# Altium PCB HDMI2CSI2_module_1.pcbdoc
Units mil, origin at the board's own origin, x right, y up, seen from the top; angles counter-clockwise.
Board outline 4245 x 2835 mil, 4 copper layers (Top Layer, Inner1, Inner2, Bottom Layer); 51 components, 44 nets, 240 pads, 137 vias.
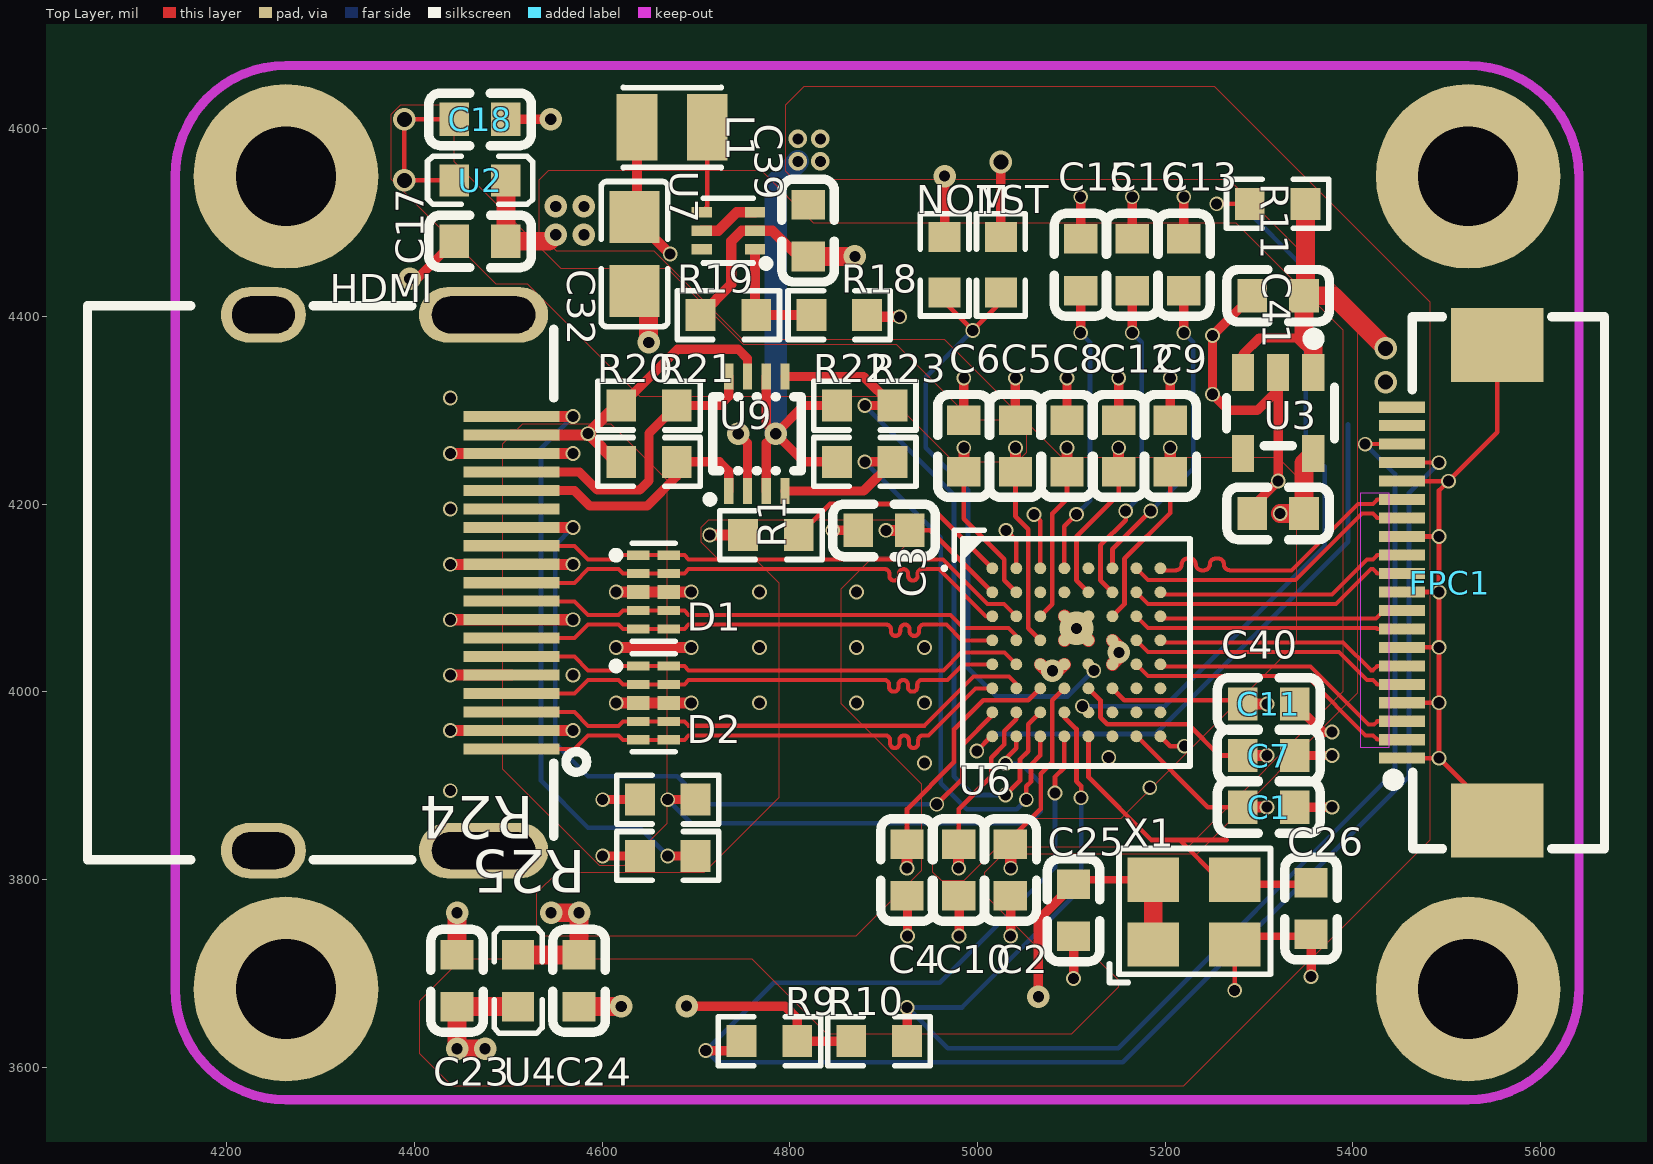
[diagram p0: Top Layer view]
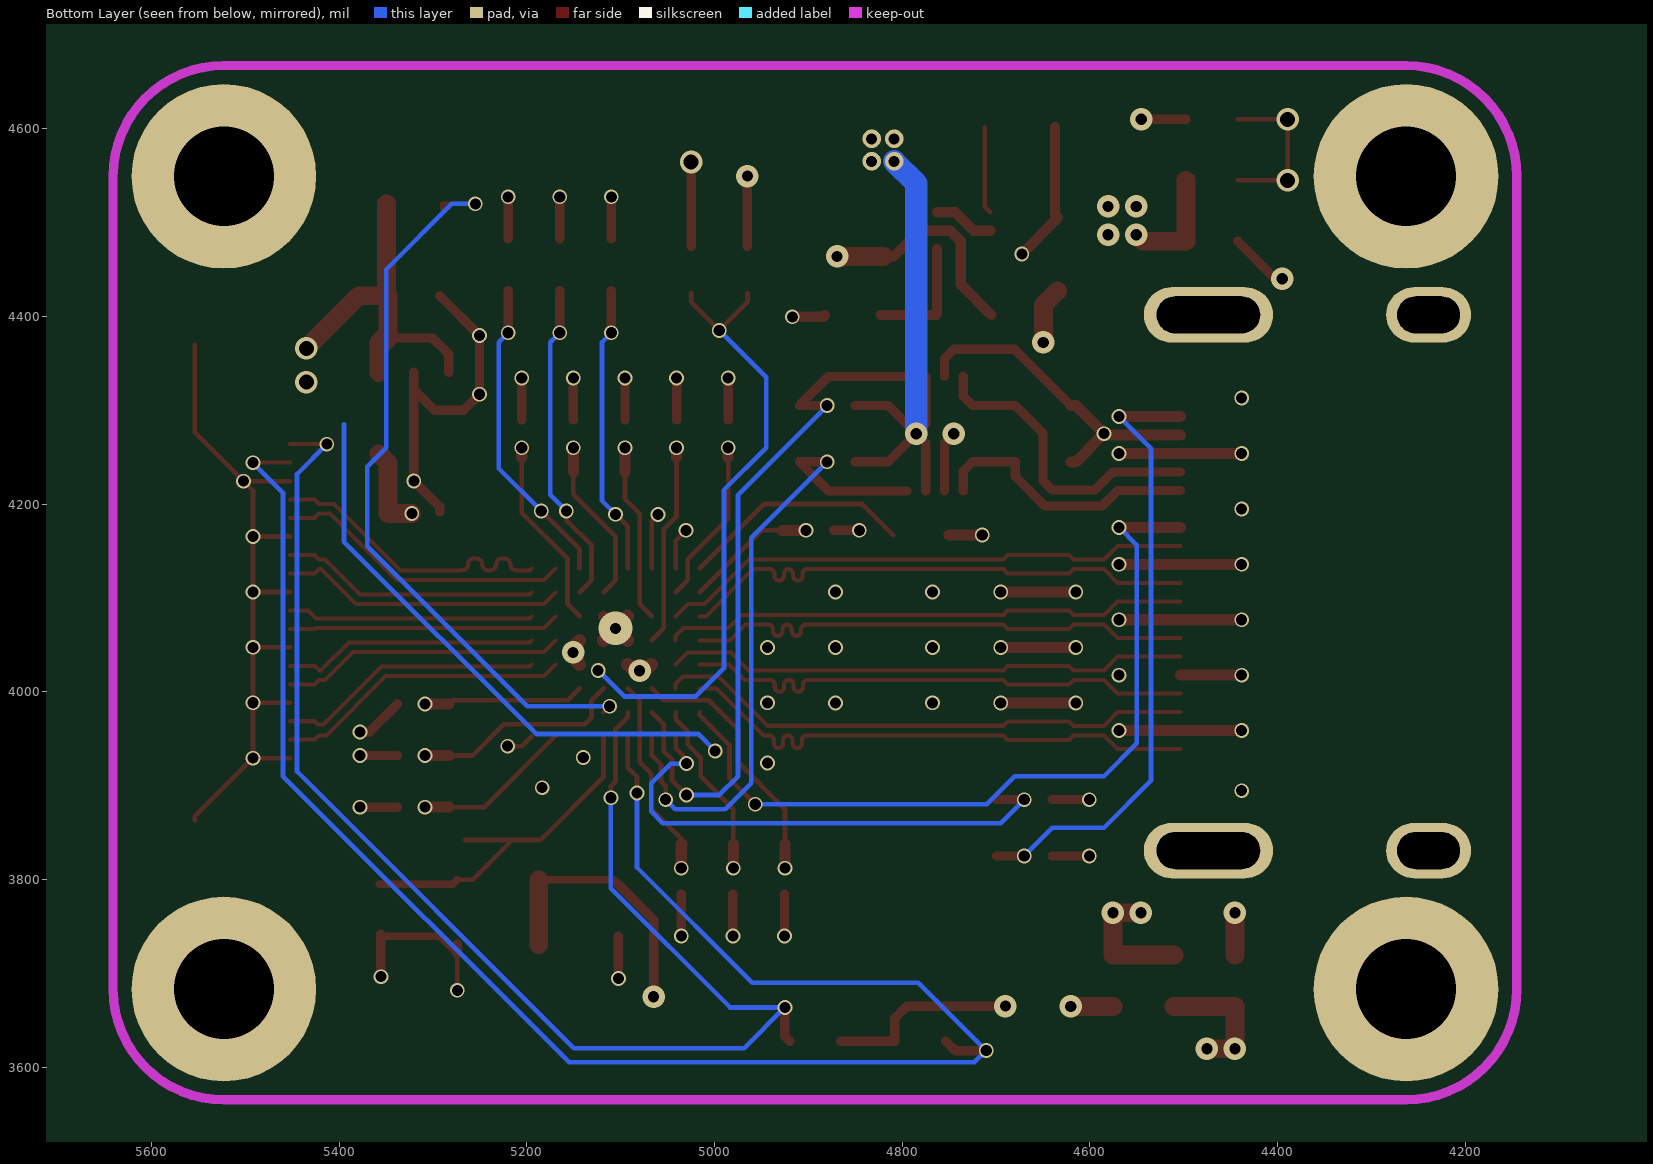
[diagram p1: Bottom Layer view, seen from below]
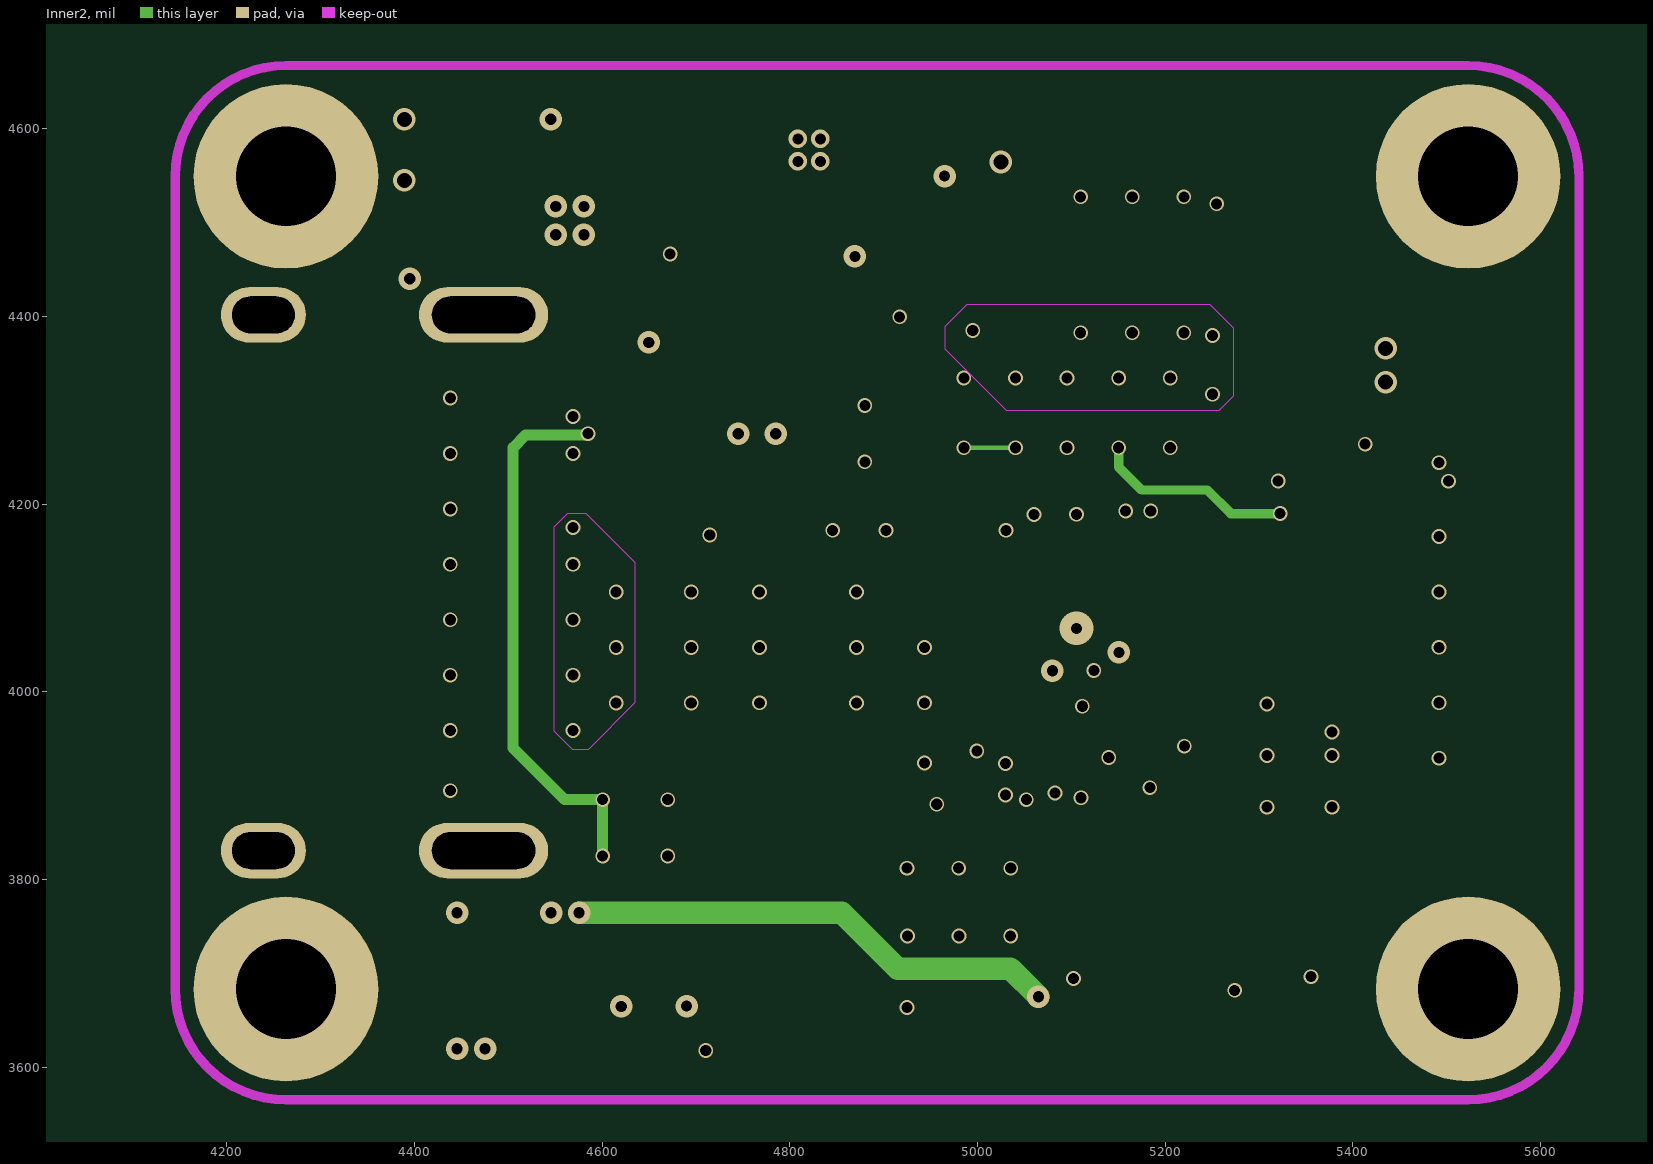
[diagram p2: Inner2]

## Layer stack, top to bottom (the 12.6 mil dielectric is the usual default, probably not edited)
Top Layer: signal copper (thickness not stored)
Dielectric: dielectric 12.6, FR-4, Dk 4.8
Inner1: signal copper (thickness not stored)
Dielectric: dielectric 12.6, FR-4, Dk 4.8
Inner2: signal copper (thickness not stored)
Dielectric: dielectric 12.6, FR-4, Dk 4.8
Bottom Layer: signal copper (thickness not stored)

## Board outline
6995,2750 2750,2750 2750,5585 6995,5585

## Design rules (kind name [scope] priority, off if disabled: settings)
BoardOutlineClearance copperThickness1oz [All] p0: genericclearance=10 ignorepadtopadclearanceinfootprint=FALSE except(0: Arc-SplitContinuation Track-SplitContinuation SMDPad-SplitContinuation THPad-SplitContinuation Via-SplitContinuation Fill-SplitContinuation Poly-SplitContinuation Region-SplitContinuation Text-SplitContinuation; 6: SMDPad-CutoutEdge THPad-CutoutEdge Via-CutoutEdge Fill-CutoutEdge Region-CutoutEdge; 11.8: Track-OutlineEdge SMDPad-OutlineEdge THPad-OutlineEdge Via-OutlineEdge Fill-OutlineEdge Region-OutlineEdge Poly-OutlineEdge Text-OutlineEdge Track-CutoutEdge)
BoardOutlineClearance copperThickness2oz [All] p0: genericclearance=10 ignorepadtopadclearanceinfootprint=FALSE except(0: Arc-SplitContinuation Track-SplitContinuation SMDPad-SplitContinuation THPad-SplitContinuation Via-SplitContinuation Fill-SplitContinuation Poly-SplitContinuation Region-SplitContinuation Text-SplitContinuation; 6: SMDPad-CutoutEdge THPad-CutoutEdge Via-CutoutEdge Fill-CutoutEdge Region-CutoutEdge; 11.8: Track-OutlineEdge SMDPad-OutlineEdge THPad-OutlineEdge Via-OutlineEdge Fill-OutlineEdge Region-OutlineEdge Poly-OutlineEdge Text-OutlineEdge Track-CutoutEdge)
BoardOutlineClearance copperThicknessInner0.5oz [All] p0: genericclearance=10 ignorepadtopadclearanceinfootprint=FALSE except(0: Arc-SplitContinuation Track-SplitContinuation SMDPad-SplitContinuation THPad-SplitContinuation Via-SplitContinuation Fill-SplitContinuation Poly-SplitContinuation Region-SplitContinuation Text-SplitContinuation; 6: SMDPad-CutoutEdge THPad-CutoutEdge Via-CutoutEdge Fill-CutoutEdge Region-CutoutEdge; 11.8: Track-OutlineEdge SMDPad-OutlineEdge THPad-OutlineEdge Via-OutlineEdge Fill-OutlineEdge Region-OutlineEdge Poly-OutlineEdge Text-OutlineEdge Track-CutoutEdge)
Clearance copperThickness1oz [(InNet('$1N490') OR InNet('$1N473') OR InNet('$1N491') OR InNet('3V3') OR InNet('1V2') OR InNet('2V5') OR InNet('GND') OR InNet('$1N487') OR InNet('$1N3181') OR InNet('A3V3') OR InNet('A1V2') OR InNet('HDMISDA') OR InNet('HDMISCL') OR InNet('HDMI2+') OR InNet('HDMI2-') OR InNet('HDMI1+') OR InNet('HDMI1-') OR InNet('HDMI0+') OR InNet('HDMI0-') OR InNet('HDMICLK+') OR InNet('HDMICLK-') OR InNet('HDMIHPD') OR InNet('HOST_SDA') OR InNet('HOST_SCL') OR InNet('HDMI5V') OR InNet('HDMICEC') OR InNet('$1N13322') OR InNet('CSID3P') OR InNet('CSID2P') OR InNet('CSICN') OR InNet('CSID1P') OR InNet('CSID0P') OR InNet('CSICP') OR InNet('CSID3N') OR InNet('CSID2N') OR InNet('CSID1N') OR InNet('CSID0N') OR InNet('$1N17874') OR InNet('$1N34238') OR InNet('$1N34236') OR InNet('HDMISDA_5V') OR InNet('HDMISCL_5V') OR InNet('HDMIHPDI') OR InNet('HDMIHPDO'))] p1: gap=7 ignorepadtopadclearanceinfootprint=FALSE except(4: Track-Track Track-SMDPad SMDPad-SMDPad Track-Via SMDPad-Via THPad-Via Via-Via; 6: Track-THPad SMDPad-THPad THPad-THPad Track-Fill SMDPad-Fill THPad-Fill Via-Fill Fill-Fill SMDPad-Region THPad-Region Via-Region Fill-Region Region-Region Track-Poly SMDPad-Poly THPad-Poly Via-Poly Fill-Poly Poly-Poly Track-Text SMDPad-Text THPad-Text Via-Text Fill-Text Region-Text Poly-Text Text-Text; 6.9: Track-Hole SMDPad-Hole THPad-Hole Via-Hole Fill-Hole Region-Hole Poly-Hole Text-Hole Sheet-Hole; 11.8: Track-Region Region-Poly Track-Sheet SMDPad-Sheet THPad-Sheet Via-Sheet Fill-Sheet Region-Sheet Poly-Sheet Text-Sheet)
Clearance copperThickness2oz [All] p1: gap=7 ignorepadtopadclearanceinfootprint=FALSE except(6: Track-SMDPad SMDPad-SMDPad Track-THPad SMDPad-THPad THPad-THPad Track-Via SMDPad-Via THPad-Via Via-Via Track-Fill SMDPad-Fill THPad-Fill Via-Fill Fill-Fill SMDPad-Region THPad-Region Via-Region Fill-Region Region-Region Track-Poly SMDPad-Poly THPad-Poly Via-Poly Fill-Poly Poly-Poly Track-Text SMDPad-Text THPad-Text Via-Text Fill-Text Region-Text Poly-Text Text-Text; 6.9: Track-Hole SMDPad-Hole THPad-Hole Via-Hole Fill-Hole Region-Hole Poly-Hole Text-Hole Sheet-Hole; 8: Track-Track; 11.8: Track-Region Region-Poly Track-Sheet SMDPad-Sheet THPad-Sheet Via-Sheet Fill-Sheet Region-Sheet Poly-Sheet Text-Sheet)
Clearance copperThicknessInner0.5oz [All] p1: gap=7 ignorepadtopadclearanceinfootprint=FALSE except(3.5: Track-Track; 6: Track-SMDPad SMDPad-SMDPad Track-THPad SMDPad-THPad THPad-THPad Track-Via SMDPad-Via THPad-Via Via-Via Track-Fill SMDPad-Fill THPad-Fill Via-Fill Fill-Fill SMDPad-Region THPad-Region Via-Region Fill-Region Region-Region Track-Poly SMDPad-Poly THPad-Poly Via-Poly Fill-Poly Poly-Poly Track-Text SMDPad-Text THPad-Text Via-Text Fill-Text Region-Text Poly-Text Text-Text; 6.9: Track-Hole SMDPad-Hole THPad-Hole Via-Hole Fill-Hole Region-Hole Poly-Hole Text-Hole Sheet-Hole; 11.8: Track-Region Region-Poly Track-Sheet SMDPad-Sheet THPad-Sheet Via-Sheet Fill-Sheet Region-Sheet Poly-Sheet Text-Sheet)
DiffPairsRouting differentialPair [All] p1: maxuncoupledlength=10 minlimit=6 maxlimit=6 mostfreqgap=6 toplayer_minwidth=4.3 toplayer_prefwidth=4.3 toplayer_maxwidth=100 bottomlayer_minwidth=4.3 bottomlayer_prefwidth=4.3 bottomlayer_maxwidth=100 midlayer1_minwidth=4.3 midlayer1_prefwidth=4.3 midlayer1_maxwidth=100 midlayer2_minwidth=4.3 midlayer2_prefwidth=4.3 midlayer2_maxwidth=100
PasteMaskExpansion pasteMaskExpansion [All] p1: expansion=0
PlaneConnect innerPlane [All] p1: planeconnectstyle=Relief reliefexpansion=20 reliefentries=4 reliefconductorwidth=10 reliefairgap=10
PolygonConnect copperRegion [All] p1: connectstyle=Direct reliefentries=4 reliefconductorwidth=10 polygonreliefangle="90 Angle" airgapwidth=10
RoutingVias viaSize [All] p1: viastyle="Through Hole" holewidth=12 minholewidth=7.9 maxholewidth=248 width=24 minwidth=11.8 maxwidth=393.7
SolderMaskExpansion solderMaskExpansion [All] p1: useseparateexpansions=TRUE expansion=2 expansionbottom=2
Width copperThickness1oz [All] p1: maxlimit=100 minlimit=4 preferedwidth=10
Width copperThickness2oz [All] p1: maxlimit=100 minlimit=8 preferedwidth=10
Width copperThickness0.5oz [All] p1: maxlimit=100 minlimit=4 preferedwidth=10

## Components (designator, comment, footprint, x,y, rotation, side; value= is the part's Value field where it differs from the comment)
C1 "CGA0603X7R104K500JT" C0603 5310.5,3877 r180 top
C2 "CGA0603X7R104K500JT" C0603 5035,3810 r90 top
C3 "CGA0603X7R104K500JT" C0603 4900.5,4172 r0 top
C4 "CGA0603X7R104K500JT" C0603 4925,3810 r90 top
C5 "CGA0603X7R104K500JT" C0603 5040.5,4262 r270 top
C6 "CGA0603X7R104K500JT" C0603 4985.5,4262 r270 top
C7 "CGA0603X7R104K500JT" C0603 5310.5,3932 r180 top
C8 "CGA0603X7R104K500JT" C0603 5095.5,4262 r270 top
C9 "CGA0603X7R104K500JT" C0603 5205.5,4262 r270 top
C10 "CGA0603X7R104K500JT" C0603 4980,3810 r90 top
C11 "CGA0603X7R104K500JT" C0603 5310.5,3987 r180 top
C12 "CGA0603X7R104K500JT" C0603 5150.5,4262 r270 top
C13 "CGA0603X7R104K500JT" C0603 5220,4455 r90 top
C15 "CGA0603X7R104K500JT" C0603 5110,4455 r90 top
C16 "CGA0603X7R104K500JT" C0603 5165,4455 r90 top
C17 "CL10A105KB8NNNC" C0603 4470,4480 r0 top
C18 "CGA0603X7R104K500JT" C0603 4470,4610 r180 top
C23 "CL10A105KB8NNNC" C0603 4445.5,3692 r270 top
C24 "CGA0603X7R104K500JT" C0603 4575.5,3692 r90 top
C25 "CGA0603X7R104K500JT" C0603 5102.53,3767.09 r90 top
C26 "CL10C150JB8NNNC" C0603 5355.59,3769.03 r90 top
C32 "CL21A226MAQNNNE" C0805 4634.61,4466.42 r90 top
C39 "CL10A105KB8NNNC" C0603 4819.61,4491.42 r90 top
C40 "CL10A105KB8NNNC" C0603 5320.5,4190 r0 top
C41 "CL10A105KB8NNNC" C0603 5320.5,4422 r0 top
D1 "TPD4E05U06DQAR_C138714" USON-10_L2.5-W1.0-P0.50-BL 4655,4106.2 r270 top
D2 "TPD4E05U06DQAR_C138714" USON-10_L2.5-W1.0-P0.50-BL 4655,3988.1 r270 top
FPC1 "FPC-05F-20PH20" FPC-SMD_20P-P0.50_XUNPU_FPC-05F-20PH20 5503.27,4116.18 r90 top
HDMI "HDMI-001S" HDMI-SMD_HDMI-001S 4371.38,4116.18 r270 top
L1 "WPN252012H1R0MT" IND-SMD_L2.5-W2.0_WPN252012H 4674.61,4601.42 r180 top
NOM "0603WAF1002T5E" R0603 4965,4455 r90 top
R1 "0603WAF2001T5E" R0603 4780,4167 r180 top
R9 "0603WAF4701T5E" R0603 4778.38,3627.57 r180 top
R10 "0603WAF4701T5E" R0603 4895.18,3627.57 r0 top
R11 "0603WAF1002T5E" R0603 5320,4520 r180 top
R18 "Res_0603" R0603 4852.7,4401.43 r0 top
R19 "Res_0603" R0603 4734.61,4401.42 r0 top
R20 "0603WAF4702T5E" R0603 4650,4245 r180 top
R21 "0603WAF4702T5E" R0603 4650,4305 r180 top
R22 "0603WAF4702T5E" R0603 4880,4305 r0 top
R23 "0603WAF4702T5E" R0603 4880,4245 r0 top
R24 "0603WAF1002T5E" R0603 4670,3885 r180 top
R25 "0603WAF1002T5E" R0603 4670,3825 r180 top
TST "0603WAF1002T5E" R0603 5025,4455 r270 top
U2 "BLM18EG221SN1D" L0603 4470,4545 r180 top
U3 "TLV75725PDBVR" SOT-23-5_L2.9-W1.6-P0.95-LS2.8-BR 5320.5,4297 r90 top
U4 "BLM18EG221SN1D" L0603 4510.5,3692 r90 top
U6 "TC358743XBG" BGA-64_L6.0-W6.0-W8-R8-P0.65-D0.40-TL 5105.5,4042 r0 top
U7 "TLV62568ADRLR" SOT-563_L1.6-W1.2-P0.50-LS1.6-BL 4734.61,4491.42 r90 top
U9 "TXS0102DCUR" VSON8_L2.0-W2.3-P0.50-LS3.1-BL 4765,4275 r0 top
X1 "OT2EL4C4JI-111OLP-27M" OSC-SMD_4P-L3.2-W2.5-BL 5230.8,3765.15 r0 top

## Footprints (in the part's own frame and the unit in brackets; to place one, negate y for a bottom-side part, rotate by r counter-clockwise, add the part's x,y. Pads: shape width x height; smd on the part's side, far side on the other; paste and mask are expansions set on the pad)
BGA-64_L6.0-W6.0-W8-R8-P0.65-D0.40-TL [mm]
  round 0.32 smd: A1(-2.275,2.275) A2(-1.625,2.275) A3(-0.975,2.275) A4(-0.325,2.275) A5(0.325,2.275) A6(0.975,2.275) A7(1.625,2.275) A8(2.275,2.275) B1(-2.275,1.625) B2(-1.625,1.625) B3(-0.975,1.625) B4(-0.325,1.625) B5(0.325,1.625) B6(0.975,1.625) B7(1.625,1.625) B8(2.275,1.625) C1(-2.275,0.975) C2(-1.625,0.975) C3(-0.975,0.975) C4(-0.325,0.975) C5(0.325,0.975) C6(0.975,0.975) C7(1.625,0.975) C8(2.275,0.975) D1(-2.275,0.325) D2(-1.625,0.325) D3(-0.975,0.325) D4(-0.325,0.325) D5(0.325,0.325) D6(0.975,0.325) D7(1.625,0.325) D8(2.275,0.325) E1(-2.275,-0.325) E2(-1.625,-0.325) E3(-0.975,-0.325) E4(-0.325,-0.325) E5(0.325,-0.325) E6(0.975,-0.325) E7(1.625,-0.325) E8(2.275,-0.325) F1(-2.275,-0.975) F2(-1.625,-0.975) F3(-0.975,-0.975) F4(-0.325,-0.975) F5(0.325,-0.975) F6(0.975,-0.975) F7(1.625,-0.975) F8(2.275,-0.975) G1(-2.275,-1.625) G2(-1.625,-1.625) G3(-0.975,-1.625) G4(-0.325,-1.625) G5(0.325,-1.625) G6(0.975,-1.625) G7(1.625,-1.625) G8(2.275,-1.625) H1(-2.275,-2.275) H2(-1.625,-2.275) H3(-0.975,-2.275) H4(-0.325,-2.275) H5(0.325,-2.275) H6(0.975,-2.275) H7(1.625,-2.275) H8(2.275,-2.275)
  silkscreen extent -3.63,-3.08 3.08,3.3
C0603 [mm]
  rect 0.8x0.9 smd: 1(-0.7,0) 2(0.7,0)
  silkscreen extent -1.39,-0.71 1.39,0.71
C0805 [mm]
  rect 1.41x1.35 smd: 1(-1,0) 2(1,0)
  silkscreen extent -1.96,-0.9 1.96,0.9
FPC-SMD_20P-P0.50_XUNPU_FPC-05F-20PH20 [mm]
  rect 0.3x1.25 smd: 1(-4.75,1.288) 2(-4.25,1.288) 3(-3.75,1.288) 4(-3.25,1.288) 5(-2.75,1.288) 6(-2.25,1.288) 7(-1.75,1.288) 8(-1.25,1.288) 9(-0.75,1.288) 10(-0.25,1.288) 11(0.25,1.288) 12(0.75,1.288) 13(1.25,1.288) 14(1.75,1.288) 15(2.25,1.288) 16(2.75,1.288) 17(3.25,1.288) 18(3.75,1.288) 19(4.25,1.288) 20(4.75,1.288)
  rect 2x2.5 smd: 21(6.44,-1.287) 22(-6.44,-1.287)
  silkscreen extent -7.2,-4.19 7.2,1.67
HDMI-SMD_HDMI-001S [mm]
  rect 0.3x2.6 smd: 1(4.5,3.36) 2(4,3.36) 3(3.5,3.36) 4(3,3.36) 5(2.5,3.36) 6(2,3.36) 7(1.5,3.36) 8(1,3.36) 9(0.5,3.36) 10(0,3.36) 11(-0.5,3.36) 12(-1,3.36) 13(-1.5,3.36) 14(-2,3.36) 15(-2.5,3.36) 16(-3,3.36) 17(-3.5,3.36) 18(-4,3.36) 19(-4.5,3.36)
  oval 1.5x3.5 hole 1 slot 2.8 at 90 deg: 20(-7.25,2.6) 21(7.25,2.6)
  oval 1.5x2.3 hole 1 slot 1.7 at 90 deg: 22(-7.25,-3.36) 23(7.25,-3.36)
  silkscreen extent -7.5,-8.12 7.5,5.39
IND-SMD_L2.5-W2.0_WPN252012H [mm]
  rect 1.1x1.8 smd: 1(-0.95,0) 2(0.95,0)
  silkscreen extent -1.33,-1.09 1.33,1.09
L0603 [mm]
  rect 0.8x0.864 smd: 1(-0.7,0) 2(0.7,0)
  silkscreen extent -1.42,-0.65 1.42,0.65
OSC-SMD_4P-L3.2-W2.5-BL [mm]
  rect 1.4x1.2 smd: 1(-1.1,-0.875) 2(1.1,-0.875) 3(1.1,0.875) 4(-1.1,0.875)
  silkscreen extent -2.29,-1.9 2.07,1.72
R0603 [mil]
  rect 31.75x34.02 smd: 1(-29.66,0) 2(29.66,0)
  silkscreen extent -55,-26 55,26
SOT-23-5_L2.9-W1.6-P0.95-LS2.8-BR [mm]
  rect 1x0.6 smd: 1(1.1,-0.95) 2(1.1,0) 3(1.1,0.95) 4(-1.1,0.95) 5(-1.1,-0.95)
  silkscreen extent -0.89,-1.52 2.16,1.4
SOT-563_L1.6-W1.2-P0.50-LS1.6-BL [mm]
  rect 0.28x0.545 smd: 1(-0.5,-0.723) 2(0,-0.723) 3(0.5,-0.723) 4(0.5,0.723) 5(0,0.723) 6(-0.5,0.723)
  silkscreen extent -0.99,-1.12 0.88,0.68
USON-10_L2.5-W1.0-P0.50-BL [mm]
  rect 0.25x0.609 smd: 1(-1,-0.415) 2(-0.5,-0.415) 4(0.5,-0.415) 5(1,-0.415) 6(1,0.415) 7(0.5,0.415) 9(-0.5,0.415) 10(-1,0.415)
  rect 0.38x0.609 smd: 3(0,-0.415) 8(0,0.415)
  silkscreen extent -1.33,-1.12 1.33,0.58
VSON8_L2.0-W2.3-P0.50-LS3.1-BL [mil]
  rect 9.84x27.56 smd: 1(-30,-61.02) 2(-10,-61.02) 3(10,-61.02) 4(30,-61.02) 5(30,61.02) 6(10,61.02) 7(-10,61.02) 8(-30,61.02)
  silkscreen extent -54,-74 47,39

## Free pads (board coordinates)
  round 196.85 hole 106.3: 1(4263.11,3683.11) 1(4263.11,4549.25) 1(5522.95,3683.11) 1(5522.95,4549.25)

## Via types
v1: diameter 15.7, hole 11.8, Top Layer to Bottom Layer, 106 vias
v2: diameter 24, hole 12, Top Layer to Bottom Layer, 19 vias
v3: diameter 24, hole 16, Top Layer to Bottom Layer, 5 vias
v4: diameter 19.7, hole 11.8, Top Layer to Bottom Layer, 4 vias
v5: diameter 24, hole 11.8, Top Layer to Bottom Layer, 2 vias
v6: diameter 36, hole 11.8, Top Layer to Bottom Layer, 1 vias

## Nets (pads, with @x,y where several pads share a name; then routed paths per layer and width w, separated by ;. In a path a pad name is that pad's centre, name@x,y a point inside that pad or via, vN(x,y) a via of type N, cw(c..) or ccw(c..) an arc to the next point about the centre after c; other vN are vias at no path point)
1V2: C7.2 C8.2 C9.2 C10.2 C11.2 C17.2 C32.2 L1.2 R18.2 U2.1 U6.C3 U6.C6 U6.F5 U6.F6 U6.G2 | length 1298.5
  Top Layer w5: C10.2 4980,3875 5014.69,3909.69 5014.69,3929.76 5028.72,3943.79 5028.72,3957.73 5041.52,3970.53 U6.G2 ; U6.C3 5079.91,4093.19 5079.91,4189.91 5095.5,4205.5 C8.2 ; U6.F5 5131.09,3990.82 5131.09,3972.72 5138.59,3965.22 5224.77,3965.23 5258,3932 C7.2 ; U6.F6 5156.68,3990.82 5279.12,3990.82 C11.2 ; U6.C6 5156.69,4093.19 5156.69,4141.69 5205.5,4190.5 C9.2@5205.5,4249.44
  Top Layer w11: L1.2 4637.21,4508.39 C32.2 4634.61,4504.38 v1(4672.57,4466.42) ; R18.2 4884.25,4399.55 v1(4917.2,4399.55)
  Top Layer w11.8: v1(4980,3812) C10.2 ; C8.2 v1(5095.5,4260) ; C9.2@5205.5,4249.44 v1(5205.5,4260) ; C7.2 v1(5308.5,3932) ; C11.2 v1(5308.5,3987)
  Top Layer w20: U2.1 C17.2 4543.57,4480 v2(4550.7,4487.13)
  other v2: 4580.7,4487.13 4550.7,4517.13 4580.7,4517.13
2V5: C12.2 C40.2 U3.5 U6.B5 | length 484.4
  Top Layer w5: U6.B5 5105.5,4118.78 5105.5,4165.27 5150.5,4210.27 C12.2
  Top Layer w11.8: C12.2 v1(5150.5,4260)
  Top Layer w20: v1(5322.69,4189.88) 5347.94,4189.88 C40.2 5348.06,4243.84 U3.5
  Inner2 w10: v1(5150.5,4260) 5150.5,4239.5 5175,4215 5245,4215 5270.12,4189.88 v1(5322.69,4189.88)
3V3: C1.2 C2.2 C23.2 C39.2 C41.2 FPC1.19 FPC1.20 R9.1 R10.1 R11.1 R22.1 R23.1 TST.1 U3.1 U3.3 U4.1 U6.F4 U6.H7 U7.3 U7.5 U9.3 U9.6 | length 1874.8
  Top Layer w5: C2.2 5035,3842.7 5067.4,3875.1 5067.4,3912.4 5079.9,3924.9 5079.9,3990.81 U6.F4 ; U6.H7 5170.07,3952.43 5245.5,3877 C1.2
  Top Layer w9.8: U9.3 4775,4265 v2(4785,4275) ; U9.6 4775,4285 v2(4785,4275) ; R23.1 4815,4245 v2(4785,4275) ; R22.1 4815,4305 v2(4785,4275)
  Top Layer w10: v2(4690,3665) 4795,3665 4808.04,3651.96 R9.1 R10.1 ; TST.1@5025,4474.69 v3(5025,4564.53) ; U3.3 5283.11,4359.61 5300.5,4377 5340.5,4377 U3.1@5357.9,4359.6
  Top Layer w11: U7.5 4723.98,4491.41 4743.67,4511.1 U7.3
  Top Layer w11.8: C2.2 5035.5,3837.06 v1(5035.5,3812) ; C1.2 v1(5308.5,3877)
  Top Layer w20: v2(4445.49,3619.58) v2(4475.35,3619.57) ; v2(4445.49,3619.58) C23.2 U4.1 ; R11.1 5349.66,4423.6 C41.2 ; U3.1 5357.9,4359.6 5357.9,4372.1 5348.06,4381.94 C41.2 ; v3(5435,4366) 5379,4422 C41.2
  Bottom Layer w24: v2(4785,4275) 4785,4541.43 v4(4808.7,4565.13)
  other v3: 5435,4330
  other v4: 4832.7,4565.13 4808.7,4589.13 4832.7,4589.13
$1N473: C16.1 U6.B6 | length 349.1
  Top Layer w5: U6.B6 5131.09,4118.78 5131.09,4156.09 5157.97,4182.97 v1(5157.97,4192.66)
  Top Layer w10: v1(5165,4382.59) C16.1
  Bottom Layer w5: v1(5157.97,4192.66) 5175,4209.69 5175,4372.59 v1(5165,4382.59)
$1N487: R1.1 U6.A1 | length 248.3
  Top Layer w5: R1.1 4842.66,4200 4947.5,4200 U6.A1
$1N490: C13.1 U6.A6 | length 335.7
  Top Layer w5: U6.A6 5143.89,4151.8 v1(5184.74,4192.66)
  Top Layer w10: v1(5220,4382.59) C13.1
  Bottom Layer w5: v1(5184.74,4192.66) 5230,4237.91 5230,4372.59 v1(5220,4382.59)
$1N491: C15.1 U6.A4 | length 311.3
  Top Layer w5: U6.A4 5092.7,4176.24 v1(5105.5,4189.05)
  Top Layer w10: v1(5110,4382.59) C15.1
  Bottom Layer w5: v1(5105.5,4189.05) 5120,4203.54 5120,4372.59 v1(5110,4382.59)
$1N3181: NOM.1 TST.2 U6.E5 | length 662.9
  Top Layer w5: NOM.1 4965,4415 v1(4995,4385) 5025,4415 TST.2
  Bottom Layer w5: v1(4995,4385) 4945,4335 4945,4260 4990,4215 4990,4025 5020,3995 5096.39,3995 v1(5124.1,4022.71)
$1N13322: C26.2 U6.H5 X1.3 | length 379.9
  Top Layer w5: U6.H5 5118.3,3909.2 5185.5,3842 5215.5,3842 ; 5265.5,3842 5215.5,3842 ; X1.3 5257.9,3799.6 5215.5,3842
  Top Layer w8: X1.3 5279.05,3794.65 C26.2@5357.53,3794.65
$1N17874: R11.2 U6.G5 | length 805.4
  Top Layer w5: v1(5111.8,3984.51) U6.G5 ; v1(5255,4520) 5290,4520 5290.34,4519.66 R11.2@5290.34,4515
  Bottom Layer w5: v1(5111.8,3984.51) 5199.51,3984.51 5370,4155 5370,4240 5350,4260 5350,4450 5280,4520 v1(5255,4520)
$1N34236: R18.1 R19.2 U7.1 | length 129.6
  Top Layer w11: U7.1 4763.06,4402.64 R19.2 R18.1
$1N34238: L1.1 U7.4 | length 92.7
  Top Layer w5: U7.4 4712.01,4516.95 L1.1
A1V2: C5.2 C6.2 C18.2 U2.2 U6.B2 U6.D3 | length 619.8
  Top Layer w5: U2.2 v3(4389.27,4545) v3(4389.27,4610.01) C18.2 ; C6.2@4985.5,4249.44 4985.5,4184.5 5028.72,4141.28 5028.72,4118.78 U6.B2 ; C5.2@5040.5,4249.44 5040.5,4187 5054.32,4173.18 5054.32,4067.59 U6.D3
  Top Layer w11.8: C6.2@4985.5,4249.44 v1(4985.5,4260) ; C5.2@5040.5,4249.44 v1(5040.5,4260)
  Inner2 w5: v1(4985.5,4260) v1(5040.5,4260)
A3V3: C3.2 C4.2 C24.2 C25.2 R1.2 U4.2 U6.B1 U6.F3 X1.1 X1.4 | length 1412.4
  Top Layer w5: C4.2 4925,3875 4975,3925 4975,3959.68 5006.14,3990.82 5054.32,3990.82 U6.F3 ; C3.2 4949.91,4172 U6.B1
  Top Layer w8: C25.2 5107.47,3799.6 X1.4
  Top Layer w10: v2(5065,3675) 5065,3757.12 C25.2
  Top Layer w11.8: v1(4714.78,4167) R1.2 ; v1(4902.5,4172) C3.2 ; v1(4925,3812) C4.2
  Top Layer w20: U4.2 C24.2 v2(4575.51,3764.42) ; v2(4545.65,3764.43) v2(4575.51,3764.42) ; X1.1 X1.4
  Inner2 w24: v2(4575.51,3764.42) 4855.58,3764.42 4915,3705 5035,3705 v2(5065,3675)
CSICN: FPC1.8 U6.C7 | length 288.7
  Top Layer w4.3: U6.C7 5181.93,4067.94 5425.16,4067.94 5426.12,4066.97 FPC1.8
CSICP: FPC1.9 U6.C8 | length 261.9
  Top Layer w4.3: U6.C8 5197.22,4078.24 5424.64,4078.24 5433.05,4086.65 FPC1.9
CSID0N: FPC1.2 U6.E7 | length 316.4
  Top Layer w4.3: U6.E7 5181.93,4016.75 5350.47,4016.75 5413.67,3953.55 5421.43,3953.55 5426.12,3948.86 FPC1.2
CSID0P: FPC1.3 U6.E8 | length 285.4
  Top Layer w4.3: U6.E8 5197.22,4027.05 5354.74,4027.05 5416.65,3965.15 5422.73,3965.15 5426.12,3968.54 FPC1.3
CSID1N: FPC1.5 U6.D7 | length 302.5
  Top Layer w4.3: U6.D7 5181.93,4042.35 5385.57,4042.35 5415.31,4012.61 5421.43,4012.61 5426.12,4007.91 FPC1.5
CSID1P: FPC1.6 U6.D8 | length 272.7
  Top Layer w4.3: U6.D8 5197.22,4052.65 5389.84,4052.65 5419.58,4022.91 5421.43,4022.91 5426.12,4027.6 FPC1.6
CSID2N: FPC1.11 U6.B7 | length 305.6
  Top Layer w4.3: U6.B7 5181.93,4093.53 5382.39,4093.53 5419.58,4130.72 5421.43,4130.72 5426.12,4126.02 FPC1.11
CSID2P: FPC1.12 U6.B8 | length 275.7
  Top Layer w4.3: U6.B8 5197.22,4103.83 5378.13,4103.83 5415.31,4141.02 5421.43,4141.02 5426.12,4145.71 FPC1.12
CSID3N: FPC1.14 U6.A7 | length 319.5
  Top Layer w4.3: U6.A7 5181.93,4119.12 5339.12,4119.12 5409.78,4189.78 5421.43,4189.78 5426.12,4185.08 FPC1.14
CSID3P: FPC1.15 U6.A8 | length 318.3
  Top Layer w4.3: U6.A8 5197.22,4129.42 5211.4,4129.42 ccw(c5211.4,4135.71) 5217.69,4135.71 cw(c5223.98,4135.71) 5223.98,4142 5226.4,4142 cw(c5226.4,4135.71) 5232.69,4135.71 ccw(c5238.98,4135.71) 5238.98,4129.42 5241.4,4129.42 ccw(c5241.4,4135.71) 5247.69,4135.71 cw(c5253.98,4135.71) 5253.98,4142 5256.4,4142 cw(c5256.4,4135.71) 5262.69,4135.71 ccw(c5268.98,4135.71) 5268.98,4129.42 5334.85,4129.42 5405.51,4200.08 5421.43,4200.08 5426.12,4204.77 FPC1.15
GND: C1.1 C2.1 C3.1 C4.1 C5.1 C6.1 C7.1 C8.1 C9.1 C10.1 C11.1 C12.1 C13.2 C15.2 C16.2 C17.1 C18.1 C23.1 C24.1 C25.1 C26.1 C32.1 C39.1 C40.1 C41.1 D1.3 D1.8 D2.3 D2.8 FPC1.1 FPC1.4 FPC1.7 FPC1.10 FPC1.13 FPC1.16 FPC1.21 FPC1.22 HDMI.2 HDMI.5 HDMI.8 HDMI.11 HDMI.17 HDMI.20 HDMI.21 HDMI.22 HDMI.23 NOM.2 R19.1 U3.2 U6.A2 U6.A3 U6.C4 U6.C5 U6.D4 U6.D5 U6.D6 U6.E3 U6.E4 U6.E6 U6.H8 U7.2 U9.2 X1.2 | length 3794.9
  Top Layer w5: v1(5030.5,4172) 5041.52,4160.98 U6.A2 ; v1(5060.21,4188.92) 5067.11,4182.03 U6.A3 ; U6.H8 5205.5,3942 v1(5220.5,3942) ; v1(5274.11,3681.76) X1.2@5274.11,3720.6 ; FPC1.1 v1(5491.95,3929.17) ; FPC1.4 v1(5491.95,3988.23) ; FPC1.7 v1(5491.95,4047.28) ; FPC1.10 v1(5491.95,4106.34) ; FPC1.13 v1(5491.95,4165.39) ; FPC1.16 v1(5501.95,4224.45) ; FPC1.22 5553.96,3867.16 v1(5491.95,3929.17) ; FPC1.21 5553.96,4276.46 v1(5501.95,4224.45) ; v1(5491.95,3929.17) v1(5491.95,3988.23) ; v1(5491.95,3988.23) v1(5491.95,4047.28) ; v1(5491.95,4047.28) v1(5491.95,4106.34) ; v1(5491.95,4106.34) v1(5491.95,4165.39) ; v1(5491.95,4165.39) 5491.95,4214.45 v1(5501.95,4224.45)
  Top Layer w8: X1.2@5274.11,3720.6 5293.04,3739.53 C26.1@5355.59,3739.53
  Top Layer w9.8: v2(4745,4275) 4755,4265 U9.2
  Top Layer w10: v2(4395,4440) 4402.44,4440 C17.1 ; C18.1 v2(4545.33,4609.99) ; v1(4845.78,4172.01) C3.1 ; v1(4925.49,3739.58) C4.1@4925.5,3784.44 ; NOM.2@4965,4474.69 v2(4965,4549.53) ; v1(4980.49,3739.58) C10.1@4980.5,3784.44 ; C6.1 v1(4985.51,4334.42) ; v1(5035.49,3739.58) C2.1@5035.5,3784.44 ; C5.1 v1(5040.51,4334.42) ; C8.1 v1(5095.51,4334.42) ; v1(5102.52,3694.37) C25.1 ; C15.2 v1(5110,4527.41) ; C12.1 v1(5150.51,4334.42) ; C16.2 v1(5165,4527.41) ; C9.1 v1(5205.51,4334.42) ; C13.2 v1(5220,4527.41) ; X1.2@5274.11,3720.6 X1.2 ; C40.1@5292.94,4192 5292.94,4197 v1(5320.51,4224.56) U3.2@5320.51,4322.01 ; C41.1 v1(5250.5,4379.55) v1(5250.5,4317) 5267.57,4299.93 5298.43,4299.93 U3.2@5320.51,4322.01 ; U3.2 U3.2@5320.51,4322.01 ; C1.1 v1(5377.91,3877) ; C7.1 v1(5377.91,3932) ; C11.1 5368.06,3957 v1(5377.91,3957) ; v1(5355.58,3696.31) 5355.59,3739.53 C26.1
  Top Layer w11: R19.1 4737.7,4434.17 4737.7,4480.13 4748.98,4491.41 U7.2 4781.42,4491.41 4808.97,4463.86 C39.1
  Top Layer w11.8: v1(4438.34,3958.6) 4503.66,3958.6 v1(4568.98,3958.6) ; v1(4438.34,4017.65) HDMI.5@4503.66,4017.65 ; v1(4438.34,4076.71) 4503.66,4076.71 v1(4568.98,4076.71) ; v1(4438.34,4135.76) 4503.66,4135.76 v1(4568.98,4135.76) ; v1(4438.34,4253.88) 4503.66,4253.88 v1(4568.98,4253.88) ; v1(4614.99,3988.1) D2.3 D2.8 v1(4695.02,3988.1) ; v1(4614.98,4047.15) v1(4695.02,4047.16) ; v1(4614.98,4106.21) D1.3 D1.8 v1(4695.01,4106.21) ; v6(5105.5,4067.6) U6.C5
  Top Layer w14: U6.E3 5073.96,4022.35 v5(5079.9,4022.35) 5085.85,4022.35 U6.E4 ; U6.D4 v6(5105.5,4067.6) ; U6.C4 v6(5105.5,4067.6) ; U6.D5 v6(5105.5,4067.6) ; U6.E6 5150.74,4036.05 v5(5150.74,4042) 5150.74,4047.95 U6.D6
  Top Layer w20: C23.1 v2(4445.51,3764.42) ; C24.1 4575.64,3664.58 v2(4620.49,3664.58) ; C32.1 4649.61,4412.05 v2(4649.61,4372.2) ; C39.1 v2(4869.46,4463.86)
  other v1: 4438.34,3894.54 5183.8,3897.74 4943.72,3924.11 5140,3930 4767.69,3988.15 4871.03,3988.12 4943.72,3988.16 4568.98,4017.65 4767.69,4047.2 4871.03,4047.18 4943.7,4047.22 4767.69,4106.26 4871.03,4106.23 4438.34,4194.82 4438.34,4312.93
HDMI0+: D1.5 D1.6 HDMI.7 U6.D1 | length 560.3
  Top Layer w4.3: HDMI.7@4503.66,4057.02 4570.44,4057.02 4584.96,4071.54 4617.7,4071.53 4622.39,4066.84 D1.5 D1.6 ; D1.6@4671.32,4066.89 4687.61,4066.89 4692.3,4071.58 4902.77,4071.58 cw(c4902.77,4066.58) 4907.77,4066.58 4907.77,4064.5 ccw(c4912.77,4064.5) 4917.77,4064.5 4917.77,4066.58 cw(c4922.77,4066.58) 4927.77,4066.58 4927.77,4064.5 ccw(c4932.77,4064.5) 4937.77,4064.5 4937.77,4066.58 cw(c4942.77,4066.58) 4942.77,4071.58 4966.91,4071.58 4983.69,4054.8 U6.D1
HDMI0-: D1.4 D1.7 HDMI.9 U6.D2 | length 561.6
  Top Layer w4.3: HDMI.9@4503.66,4096.39 4570.44,4096.39 4585,4081.84 4617.7,4081.83 4622.39,4086.52 D1.4 D1.7 ; D1.7@4671.32,4086.57 4687.61,4086.57 4692.3,4081.88 4971.18,4081.88 4985.07,4067.98 5032.89,4067.98 5041.52,4059.36 U6.D2
HDMI1+: D2.2 D2.9 HDMI.4 U6.E1 | length 562
  Top Layer w4.3: HDMI.4@4503.66,3997.97 4570.44,3997.97 4584.96,4012.49 4617.7,4012.47 4622.39,4007.78 D2.2 D2.9 ; D2.9 4687.61,4007.84 4692.3,4012.54 4900.89,4012.53 cw(c4900.89,4007.53) 4905.89,4007.53 4905.89,4005 ccw(c4910.89,4005) 4915.89,4005 4915.89,4007.53 cw(c4920.89,4007.53) 4925.89,4007.53 4925.89,4005 ccw(c4930.89,4005) 4935.89,4005 4935.89,4007.53 cw(c4940.89,4007.53) 4940.89,4012.53 4968.04,4012.53 4984.71,4029.2 U6.E1
HDMI1-: D2.1 D2.10 HDMI.6 U6.E2 | length 560.7
  Top Layer w4.3: HDMI.6@4503.66,4037.34 4570.44,4037.34 4585,4022.78 4617.7,4022.78 4622.39,4027.47 D2.1 D2.10 ; D2.10 4687.61,4027.53 4692.31,4022.83 4963.77,4022.83 4982.55,4041.61 5029.11,4041.61 U6.E2
HDMI2+: D2.5 D2.6 HDMI.1 U6.F1 | length 579.6
  Top Layer w4.3: HDMI.1@4503.66,3938.91 4570.44,3938.91 4584.96,3953.43 4617.7,3953.42 4622.39,3948.73 D2.5 D2.6 ; D2.6@4671.32,3948.78 4687.61,3948.78 4692.3,3953.48 ; 4692.31,3953.47 4901.91,3953.47 cw(c4901.91,3948.47) 4906.91,3948.47 4906.91,3945 ccw(c4911.91,3945) 4916.91,3945 4916.91,3948.47 cw(c4921.91,3948.47) 4926.91,3948.47 4926.91,3945 ccw(c4931.91,3945) 4936.91,3945 4936.91,3948.47 cw(c4941.91,3948.47) 4941.91,3953.47 4948.04,3953.47 4998.18,4003.61 U6.F1
HDMI2-: D2.4 D2.7 HDMI.3 U6.F2 | length 577.2
  Top Layer w4.3: HDMI.3@4503.66,3978.28 4570.44,3978.28 4585,3963.73 ; 4585.01,3963.72 4617.7,3963.72 4622.39,3968.41 D2.4 D2.7 ; D2.7@4671.32,3968.47 4687.61,3968.47 4692.31,3963.77 4943.77,3963.77 4996.02,4016.02 5033.67,4016.02 5041.52,4008.17 U6.F2
HDMI5V: HDMI.18 R20.2 R21.2 R24.2 R25.2 U9.7 | length 1024.1
  Top Layer w9.8: v1(4600.68,3825) R25.2 ; v1(4600.68,3885) R24.2 ; R21.2 4680.34,4365 4745,4365 4755,4355 U9.7
  Top Layer w11.8: HDMI.18@4503.66,4273.56 4583.56,4273.56 v1(4585,4275) ; R20.2 4615,4245 v1(4585,4275) ; R21.2 4615,4305 v1(4585,4275)
  Inner2 w11.8: v1(4585,4275) 4583.56,4273.56 4518.56,4273.56 4505,4260 4505,3940 4560,3885 v1(4600.68,3885) v1(4600.68,3825)
HDMICEC: HDMI.13 U6.G1 | length 859.4
  Top Layer w5: v1(4956.7,3880.07) 4984.09,3907.45 4984.09,3943.18 5015.93,3975.02 U6.G1
  Top Layer w11.8: HDMI.13@4503.66,4175.14 v1(4568.98,4175.14)
  Bottom Layer w5: v1(4568.98,4175.14) 4550,4156.15 4550,3945 4585,3910 4680,3910 4709.93,3880.07 v1(4956.7,3880.07)
HDMICLK+: D1.2 D1.9 HDMI.10 U6.C1 | length 574.4
  Top Layer w4.3: HDMI.10@4503.66,4116.07 4570.44,4116.07 4584.96,4130.59 4617.7,4130.58 4622.39,4125.89 D1.2 D1.9 4687.61,4125.88 4692.3,4130.57 4901.22,4130.64 cw(c4901.22,4125.64) 4906.22,4125.64 4906.22,4123.5 ccw(c4911.22,4123.5) 4916.22,4123.5 4916.22,4125.64 cw(c4921.22,4125.64) 4926.22,4125.64 4926.22,4123.5 ccw(c4931.22,4123.5) 4936.22,4123.5 4936.22,4125.64 cw(c4941.22,4125.64) 4941.22,4130.64 4959.16,4130.64 5009.41,4080.39 U6.C1
HDMICLK-: D1.1 D1.10 HDMI.12 U6.C2 | length 572.8
  Top Layer w4.3: HDMI.12@4503.66,4155.44 4570.44,4155.44 4585,4140.89 4617.7,4140.88 4622.39,4145.57 D1.1 D1.10 4687.61,4145.57 4692.3,4140.88 4963.43,4140.94 5010.79,4093.57 5028.34,4093.57 U6.C2
HDMIHPD: HDMI.19 R25.1 | length 665.4
  Top Layer w9.8: v1(4670,3825) R25.1
  Top Layer w11.8: HDMI.19@4503.66,4293.24 v1(4568.98,4293.24)
  Bottom Layer w5: v1(4568.98,4293.24) 4535,4259.26 4535,3905 4585,3855 4640,3855 v1(4670,3825)
HDMIHPDI: R24.1 U6.H2 | length 552.6
  Top Layer w5: v1(5029.99,3923.42) 5029.99,3928.49 5041.52,3940.02 U6.H2
  Top Layer w9.8: v1(4670,3885) R24.1
  Bottom Layer w5: v1(4670,3885) 4695,3860 5055,3860 5067.4,3872.4 5067.4,3902.6 5046.58,3923.42 v1(5029.99,3923.42)
HDMIHPDO: U6.H1 | length 636
  Top Layer w5: v1(4999.39,3936.84) 5014.98,3952.43 U6.H1
  Bottom Layer w5: v1(4999.39,3936.84) 5017.55,3955 5190,3955 5395,4160 5395,4285
HDMISCL: R23.2 U6.H3 U9.4 | length 713.8
  Top Layer w5: v1(5052.1,3885) 5052.1,3899.1 5057.1,3904.1 5057.1,3922.1 5067.11,3932.11 U6.H3
  Top Layer w9.8: U9.4 4878.64,4213.98 R23.2 v1(4880,4245)
  Bottom Layer w5: v1(4880,4245) 4961,4164 4961,3902.41 4988.71,3874.7 5041.8,3874.7 v1(5052.1,3885)
HDMISCL_5V: HDMI.15 R20.1 U9.1 | length 291.8
  Top Layer w9.8: HDMI.15@4503.66,4214.5 4570.5,4214.5 4587,4198 4648,4198 4679.66,4229.66 R20.1 4725,4245 4735,4235 U9.1
HDMISDA: R22.2 U6.G3 U9.5 | length 758.2
  Top Layer w5: v1(5029.99,3890) 5045.29,3905.3 5045.29,3927.79 5054.31,3936.81 5054.31,3965.22 U6.G3
  Top Layer w9.8: U9.5 4878.64,4336.02 R22.2 v1(4880,4305)
  Bottom Layer w5: v1(4880,4305) 4975,4210 4975,3910 4995,3890 v1(5029.99,3890)
HDMISDA_5V: HDMI.16 R21.1 U9.8 | length 331.2
  Top Layer w9.8: HDMI.16@4503.66,4234.19 4575.81,4234.19 4595,4215 4640,4215 4650,4225 4650,4275.34 R21.1 4725,4305 4735,4315 U9.8
HOST_SCL: FPC1.17 R9.2 U6.H4 | length 1912
  Top Layer w4.3: FPC1.17 v1(5491.95,4244.14)
  Top Layer w5: v1(5082.7,3892) 5082.7,3909.2 5092.7,3919.2 U6.H4
  Top Layer w10: v1(4710.51,3617.57) 4743.72,3617.57 R9.2@4753.72,3627.57
  Bottom Layer w5: v1(5082.7,3892) 5082.7,3812.7 4960,3690 4782.94,3690 v1(4710.51,3617.57) 4723.08,3605 5155,3605 5460,3910 5460,4212.19 v1(5491.95,4244.14)
HOST_SDA: FPC1.18 R10.2 U6.G4 | length 1532.6
  Top Layer w4.3: v1(5413.21,4263.82) FPC1.18
  Top Layer w5: U6.G4 5092.7,3973.02 5105.5,3960.22 5105.5,3904.5 5110.5,3899.5 v1(5110.5,3887)
  Top Layer w10: R10.2@4919.84,3627.57 4925.05,3632.78 v1(4925.05,3663.57)
  Bottom Layer w5: v1(5110.5,3887) 5110.5,3790.5 4983.57,3663.57 v1(4925.05,3663.57) 4968.62,3620 5150,3620 5445,3915 5445,4232.03 v1(5413.21,4263.82)
pads on no net: HDMI.14 U3.4 U6.A5 U6.B3 U6.B4 U6.F7 U6.F8 U6.G6 U6.G7 U6.G8 U6.H6 U7.6

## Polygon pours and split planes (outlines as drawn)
GND on Bottom Layer (solid, remove dead copper, pour order 24): 3090,5335 6635,5335 6635,3000 3090,3000
GND on Inner1 (solid, remove dead copper): 3000,5130 6745,5130 6745,3060 3000,3060
GND on Top Layer (solid, remove dead copper, pour order 22): 3205,5040 6545,5040 6545,3115 3205,3115
3V3 on Top Layer (solid, remove dead copper, pour order 0): 4799.44,4495.42 4840.53,4495.42 4847.56,4502.45 4847.56,4533.95 4835.37,4546.14 4835.37,4546.15 4803.87,4546.15 4774.86,4517.13 4751.7,4517.13 4751.7,4505.13 4773.99,4505.13 4774.99,4504.13 4789.82,4504.13
3V3 on Top Layer (solid, remove dead copper, pour order 2): 4847.56,4504.35 4847.56,4595.12 4835.37,4607.32 4802.7,4607.32 4790.51,4595.13 4790.51,4504.35
$1N34238 on Top Layer (solid, remove dead copper, pour order 4): 4717.7,4505.13 4717.7,4540.13 4742.7,4565.13 4742.7,4635.13 4737.7,4640.13 4683.95,4640.13 4679.61,4635.79 4679.61,4543.22 4687.7,4535.13 4687.7,4510.13 4692.7,4505.13
1V2 on Top Layer (solid, remove dead copper, pour order 6): 4667.7,4635.13 4662.7,4640.13 4612.7,4640.13 4607.7,4635.13 4607.7,4545.13 4597.7,4535.13 4547.7,4535.13 4547.7,4470.13 4657.7,4470.13 4667.7,4480.13
1V2 on Top Layer (solid, remove dead copper, pour order 8): 4599.03,4535.13 4599.03,4470.47 4598.7,4470.13 4542.7,4470.13 4532.7,4480.13 4532.7,4525.13 4542.7,4535.13
3V3 on Top Layer (solid, remove dead copper, pour order 10): 5424.45,4274.22 5479.45,4274.22 5482.45,4277.22 5482.45,4372.22 5474.45,4380.22 5429.45,4380.22 5421.45,4372.22 5421.45,4277.22
no net on Top Layer (solid, remove dead copper, pour order 18): 4515,4285 4493.82,4263.82 4493.82,3917.93 4596.75,3815 4624.41,3815 4669.41,3860 4669.41,4225.18 4609.59,4285
no net on Top Layer (solid, remove dead copper, pour order 16): 4375,4546.7 4486.7,4435 4520,4435 4640,4315 4905,4315 4974.81,4245.19 5042.66,4245.19 5052.66,4255.19 5052.66,4277.34 5040.44,4289.56 4994.53,4289.56 4914.09,4370 4750.81,4370 4670.19,4450.62 4556.72,4450.62 4442.44,4564.9 4442.44,4610 4427.44,4625 4385,4625 4375,4615
no net on Top Layer (solid, remove dead copper, pour order 12): 4542.7,4555.24 4532.7,4545.24 4532.7,4488.55 4551.12,4470.13 4654.87,4470.13 4749.58,4375.42 4964.58,4375.42 5090,4250 5320,4250 5340,4230 5340,4051.71 5153.01,3864.72 4964.26,3864.72 4952.06,3852.53 4952.06,3808.42 4961.51,3798.97 4985.89,3798.97 5021.92,3835 5224.53,3835 5390,4000.47 5390,4385 5275.6,4499.4 4825.79,4499.4 4769.94,4555.24
no net on Top Layer (solid, remove dead copper, pour order 20): 4705,4175 4705,4160 4724.01,4140.99 4763.22,4140.99 4788.26,4115.95 4788.26,3887.13 4708.42,3807.28 4552.28,3807.28 4530,3785 4530,3745 4535,3740 4870.75,3740 4940.75,3810 4940.75,3901.37 4855,3987.12 4855,4110 4889.04,4144.04 4911.53,4144.04 4928.06,4160.57 4928.06,4177.74 4922.8,4183.01 4713.01,4183.01
no net on Top Layer (solid, remove dead copper, pour order 14): 4795,4625 4795,4555.02 4803.87,4546.15 5267.95,4546.15 5405,4409.1 5405,3998.29 5233.7,3826.99 5026.99,3826.99 5007.04,3807.04 5007.04,3784.41 5075.51,3715.95 5126.9,3715.95 5150,3692.84 5150,3685 5100,3635 4840,3635 4760,3715 4450,3715 4405,3670 4405,3615 4440,3580 5220,3580 5482.45,3842.45 5482.45,4415.31 5252.76,4645 4815,4645

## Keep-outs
Top Layer:
  region: 5408.54,4212.05 5438.58,4212.05 5438.58,3940.05 5408.54,3940.05
Inner2:
  region: 4568.08,3938.89 4585.63,3938.89 4635.31,3988.57 4635.31,4137.69 4583.08,4189.92 4563.08,4189.92 4548.4,4175.24 4548.4,3958.57
  region: 4988.48,4412.47 4965,4388.99 4965,4365.77 5030.84,4299.93 5257.57,4299.93 5273.11,4315.46 5273.11,4387.3 5247.94,4412.47
Board Outline Layer:
  lines w10: 4145,3683.11 ccw(c4263.11,3683.11) 4263.11,3565 5522.95,3565 ccw(c5522.95,3683.11) 5641.06,3683.11 5641.06,4549.25 ccw(c5522.95,4549.25) 5522.95,4667.36 4263.11,4667.36 ccw(c4263.11,4549.25) 4145,4549.25 4145,3683.11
